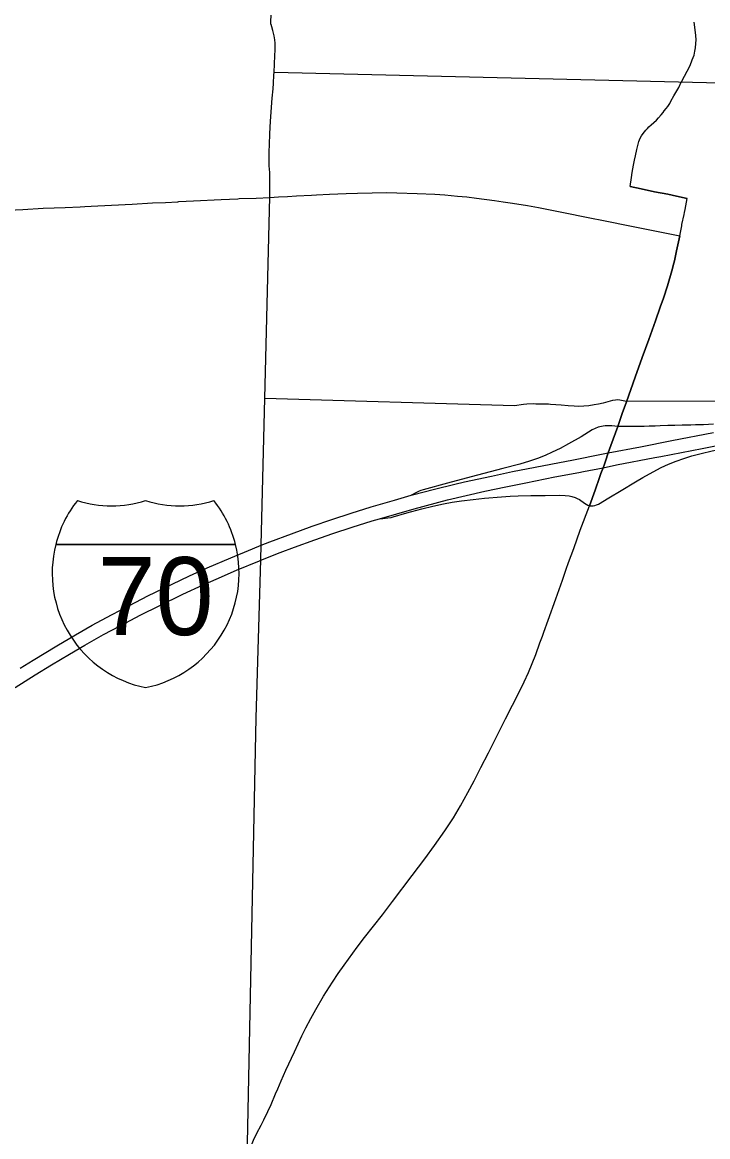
# Model space of a CAD drawing. Extents: x -29.6 to 34, y 0 to 22.
# Drawn here: x 11.502 to 12.723, y 15.537 to 17.521 of the extents above; entities that cross this region are included whole.
import ezdxf

# ---------------------------------------------------------------- set-up
doc = ezdxf.new("R2010")
doc.units = 0
for name, color, linetype in [('GM_X_Corporation', 7, 'Continuous'), ('GM_X_County_Road', 7, 'Continuous'), ('GM_X_Interchange_Ramps', 7, 'Continuous'), ('GM_X_Interstate_Route', 7, 'Continuous'), ('GM_X_Interstate_Shield', 7, 'Continuous'), ('GM_X_State_Route', 7, 'Continuous'), ('GM_X_Township', 7, 'Continuous'), ('GM_X_US_Route', 7, 'Continuous')]:
    doc.layers.add(name, color=color, linetype=linetype)

msp = doc.modelspace()

# ---------------------------------------------------------------- linework, layer by layer
at = {"layer": 'GM_X_Corporation'}
msp.add_lwpolyline([(13.0031, 16.8467), (12.5779, 16.8459), (12.5663, 16.8482), (12.5627, 16.8484), (12.5584, 16.8481), (12.5534, 16.8472), (12.545, 16.8452), (12.5365, 16.843), (12.5282, 16.8411), (12.5203, 16.8396), (12.5108, 16.8382), (12.5021, 16.8373), (12.4934, 16.837), (12.4847, 16.8372), (12.4745, 16.8379), (12.4615, 16.8392), (12.452, 16.8399), (12.4426, 16.8405), (12.439, 16.8407), (12.4317, 16.841), (12.4282, 16.8411), (12.4246, 16.8411), (12.4195, 16.8412), (12.4167, 16.8412), (12.412, 16.8413), (12.4005, 16.8408), (12.3944, 16.8403), (12.3786, 16.8382), (11.934, 16.851), (11.9428, 17.2098), (11.9426, 17.2539), (11.9422, 17.2585), (11.9418, 17.2657), (11.9416, 17.2766), (11.9418, 17.2904), (11.9421, 17.3035), (11.9429, 17.3224), (11.9441, 17.3449), (11.9472, 17.3855), (11.9485, 17.4022), (11.9493, 17.4123), (11.95, 17.4269), (11.9503, 17.4323), (13.54, 17.394)], dxfattribs=at)
at = {"layer": 'GM_X_County_Road'}
msp.add_lwpolyline([(12.5846, 17.2282), (12.604, 17.2242), (12.6282, 17.2192), (12.6517, 17.2146), (12.6674, 17.2113), (12.6862, 17.2073)], dxfattribs=at)
at = {"layer": 'GM_X_Interchange_Ramps'}
for points in [[(12.7333, 16.8051), (12.7151, 16.8044), (12.7013, 16.8039), (12.6926, 16.8036), (12.689, 16.8035), (12.6773, 16.8033), (12.6643, 16.8029), (12.6519, 16.8027), (12.6381, 16.8022), (12.6294, 16.8019), (12.6185, 16.8017), (12.6097, 16.8014), (12.5952, 16.8011), (12.5726, 16.8014), (12.5625, 16.8015)], [(12.5625, 16.8015), (12.5521, 16.8021), (12.5438, 16.8025), (12.5404, 16.8024), (12.5368, 16.802), (12.5334, 16.8015), (12.5278, 16.7998), (12.5224, 16.7976), (12.5172, 16.795), (12.5103, 16.791), (12.4972, 16.7831), (12.4751, 16.7704), (12.4597, 16.7621), (12.446, 16.7554), (12.4334, 16.7498), (12.4199, 16.7444), (12.4054, 16.7395), (12.3879, 16.7344), (12.3577, 16.7264), (12.3013, 16.7118), (12.2591, 16.7005), (12.2159, 16.6885), (12.2118, 16.6872), (12.2087, 16.6861), (12.2051, 16.6844), (12.2004, 16.682), (12.1964, 16.6798), (12.1948, 16.6788)], [(12.138, 16.6371), (12.1442, 16.6376), (12.1481, 16.638), (12.1531, 16.6384), (12.1587, 16.6394), (12.1624, 16.6405), (12.1869, 16.6474), (12.2136, 16.6547), (12.2334, 16.6595), (12.2519, 16.6635), (12.2677, 16.6663), (12.2842, 16.6688), (12.3052, 16.6714), (12.3255, 16.6734), (12.3552, 16.676), (12.3712, 16.6771), (12.385, 16.6777), (12.4076, 16.6781), (12.4331, 16.6785), (12.4585, 16.6788), (12.4687, 16.6785), (12.476, 16.6777), (12.481, 16.6767), (12.4865, 16.675), (12.4905, 16.6732), (12.4943, 16.6711), (12.5035, 16.6647), (12.5064, 16.6628), (12.5095, 16.6611), (12.512, 16.6602)]]:
    msp.add_lwpolyline(points, dxfattribs=at)
at = {"layer": 'GM_X_Interstate_Route'}
for points in [[(12.1948, 16.6788), (12.1968, 16.6794), (12.2362, 16.6898), (12.2722, 16.6987), (12.2893, 16.7026), (12.3376, 16.7128), (12.3753, 16.7211), (12.4839, 16.7417), (12.5339, 16.7519), (12.5457, 16.7542), (12.6028, 16.7653), (12.6588, 16.7765), (12.7332, 16.7906)], [(12.6289, 16.7458), (12.6394, 16.7478), (12.7132, 16.762), (12.7873, 16.7769), (12.8491, 16.7884), (12.9014, 16.7988), (12.9093, 16.8006)], [(12.4934, 16.7194), (12.5015, 16.7209), (12.5365, 16.7279), (12.5605, 16.7327), (12.6289, 16.7458)], [(12.138, 16.6371), (12.2001, 16.6545), (12.2592, 16.6707), (12.326, 16.6863), (12.3633, 16.694), (12.3986, 16.7012), (12.4503, 16.7114), (12.4934, 16.7194)], [(11.4984, 16.3712), (11.5212, 16.3854), (11.5636, 16.411), (11.5969, 16.4305), (11.6266, 16.4474), (11.6605, 16.4658), (11.6927, 16.4828), (11.7258, 16.4995), (11.769, 16.5206), (11.7999, 16.5352), (11.831, 16.5493), (11.8731, 16.5675), (11.9121, 16.5836), (11.9275, 16.5897), (11.9426, 16.5956), (11.9814, 16.6103), (12.0183, 16.6236), (12.0534, 16.6357), (12.088, 16.6471), (12.1234, 16.6582), (12.1646, 16.6703), (12.1948, 16.6788)], [(11.4893, 16.3363), (11.5249, 16.3591), (11.554, 16.3771), (11.5859, 16.3961), (11.613, 16.4118), (11.6467, 16.4307), (11.6762, 16.4466), (11.7129, 16.4659), (11.7455, 16.4822), (11.7881, 16.5028), (11.8238, 16.5193), (11.8471, 16.5297), (11.8832, 16.5452), (11.9243, 16.5621), (11.9269, 16.5632), (11.9615, 16.5769), (11.9867, 16.5865), (12.023, 16.5996), (12.0553, 16.6108), (12.0892, 16.622), (12.1254, 16.6333), (12.138, 16.6371)]]:
    msp.add_lwpolyline(points, dxfattribs=at)
at = {"layer": 'GM_X_Interstate_Shield'}
for p, q in [((11.5615, 16.5912), (11.8817, 16.5912)), ((11.8817, 16.5912), (11.5615, 16.5912)), ((11.8817, 16.5912), (11.5615, 16.5912))]:
    msp.add_line(p, q, dxfattribs=at)
for centre, start, end in [((11.7632, 16.5402), 141.669, 165.8066), ((11.6608, 16.8682), 253.0091, 286.9909), ((11.7824, 16.8682), 253.0091, 286.9909), ((11.68, 16.5402), 14.1934, 38.331), ((11.7632, 16.5402), 165.8066, 258.463), ((11.68, 16.5402), 281.537, 14.1934)]:
    msp.add_arc(centre, 0.2081, start, end, dxfattribs=at)
at = {"layer": 'GM_X_State_Route'}
msp.add_line((12.6675, 17.1137), (12.6729, 17.1404), dxfattribs=at)
for points in [[(12.6763, 17.415), (12.6913, 17.4441), (12.6954, 17.4537), (12.6984, 17.4621), (12.7001, 17.4694), (12.7009, 17.4753), (12.7018, 17.4828), (12.7021, 17.4895), (12.7019, 17.4971), (12.7007, 17.5074), (12.6985, 17.5213)], [(12.5846, 17.2282), (12.5871, 17.2446), (12.5885, 17.2534), (12.5909, 17.2662), (12.5925, 17.2751), (12.594, 17.2832), (12.5965, 17.2946), (12.5987, 17.3039), (12.6002, 17.3088), (12.6024, 17.3143), (12.6049, 17.3188), (12.6078, 17.3231), (12.6125, 17.3288), (12.6155, 17.3319), (12.6181, 17.3345), (12.6218, 17.338), (12.6315, 17.3466), (12.6354, 17.3508), (12.6401, 17.3562), (12.6433, 17.3601), (12.6455, 17.363), (12.6489, 17.3676), (12.6515, 17.3711), (12.6551, 17.3765), (12.6573, 17.3802), (12.6627, 17.3896), (12.6712, 17.4049), (12.6758, 17.414), (12.6763, 17.415)], [(12.6862, 17.2073), (12.6674, 17.2113), (12.6517, 17.2146), (12.6282, 17.2192), (12.604, 17.2242), (12.5846, 17.2282)], [(12.6729, 17.1404), (12.6765, 17.1587), (12.6769, 17.1607), (12.6806, 17.1788), (12.6814, 17.1824), (12.6824, 17.1873), (12.6862, 17.2073)], [(12.5781, 16.8453), (12.5937, 16.8892), (12.606, 16.9242), (12.6178, 16.9563), (12.6296, 16.9892), (12.6384, 17.0138), (12.644, 17.0295), (12.6512, 17.0516), (12.6591, 17.0781), (12.6626, 17.0921), (12.6636, 17.0961), (12.6675, 17.1137)], [(12.5625, 16.8015), (12.5705, 16.8242), (12.5781, 16.8453)], [(12.548, 16.7608), (12.5502, 16.7675), (12.5625, 16.8015)], [(12.512, 16.6602), (12.5222, 16.6879), (12.5302, 16.7105), (12.5327, 16.7173), (12.5365, 16.7279), (12.5381, 16.7324), (12.5405, 16.7393), (12.5457, 16.7542), (12.548, 16.7608)], [(11.9631, 15.6363), (11.9716, 15.6556), (11.9865, 15.688), (11.9998, 15.7163), (12.0068, 15.7307), (12.0156, 15.7474), (12.0245, 15.7633), (12.0386, 15.787), (12.0546, 15.8122), (12.0647, 15.8274), (12.0752, 15.8422), (12.0983, 15.874), (12.1114, 15.8914), (12.1433, 15.9321), (12.1614, 15.9558), (12.1962, 16.0016), (12.2191, 16.0318), (12.2363, 16.0553), (12.2548, 16.0815), (12.2629, 16.0936), (12.2699, 16.1048), (12.2825, 16.1261), (12.2956, 16.1497), (12.3066, 16.1702), (12.3189, 16.1943), (12.3322, 16.2201), (12.3468, 16.2487), (12.3628, 16.2805), (12.3875, 16.3293), (12.3961, 16.3469), (12.4037, 16.3635), (12.4102, 16.379), (12.4165, 16.3953), (12.424, 16.4158), (12.4285, 16.4281), (12.4311, 16.4349), (12.4385, 16.4563), (12.452, 16.4947), (12.4641, 16.5275), (12.4708, 16.5475), (12.4751, 16.5591), (12.4846, 16.5843), (12.4955, 16.6168), (12.512, 16.6602)], [(11.9028, 15.4967), (11.9042, 15.5029), (11.9067, 15.5119), (11.91, 15.5215), (11.9139, 15.5308), (11.9198, 15.5432), (11.9272, 15.5574), (11.9323, 15.5671), (11.9394, 15.5815), (11.9451, 15.5941), (11.9531, 15.6129), (11.9571, 15.6222), (11.9631, 15.6363)]]:
    msp.add_lwpolyline(points, dxfattribs=at)
at = {"layer": 'GM_X_Township'}
msp.add_lwpolyline([(11.9023, 15.4963), (11.9182, 16.2825), (11.9267, 16.5638), (11.9276, 16.5905), (11.934, 16.851), (11.9428, 17.2098), (11.9426, 17.2539), (11.9422, 17.2585), (11.9418, 17.2657), (11.9416, 17.2766), (11.9418, 17.2904), (11.9421, 17.3035), (11.9429, 17.3224), (11.9441, 17.3449), (11.9472, 17.3855), (11.9485, 17.4022), (11.9493, 17.4123), (11.95, 17.4269), (11.9503, 17.4323), (11.951, 17.4465), (11.9513, 17.4501), (11.9519, 17.458), (11.9525, 17.4748), (11.9524, 17.4835), (11.9517, 17.4893), (11.9504, 17.4964), (11.948, 17.5063), (11.9465, 17.5127), (11.9452, 17.5168), (11.9448, 17.5176), (11.975, 18.5989)], dxfattribs=at)
at = {"layer": 'GM_X_US_Route'}
msp.add_line((12.6729, 17.1404), (12.6675, 17.1137), dxfattribs=at)
for points in [[(11.4628, 17.1858), (11.5026, 17.1878), (11.5393, 17.1897), (11.5782, 17.1912), (11.6047, 17.1925), (11.6132, 17.193), (11.6247, 17.1936), (11.6605, 17.1955), (11.6977, 17.1973), (11.7338, 17.1991), (11.7572, 17.2001), (11.7792, 17.2014), (11.7808, 17.2015), (11.807, 17.2027), (11.8563, 17.2052), (11.8859, 17.2067)], [(11.8859, 17.2067), (11.8882, 17.2069), (11.9184, 17.2079), (11.943, 17.2091), (11.9581, 17.2099)], [(11.9581, 17.2099), (11.9744, 17.2109), (11.9901, 17.2119), (12.017, 17.2132), (12.0261, 17.2136)], [(12.0261, 17.2136), (12.0489, 17.2146), (12.0788, 17.216), (12.0991, 17.2168), (12.1253, 17.2173), (12.1515, 17.2175), (12.1689, 17.2173), (12.2053, 17.2161), (12.2365, 17.2146), (12.2547, 17.2134), (12.2772, 17.2115), (12.2938, 17.2099), (12.3111, 17.2077), (12.3429, 17.2035), (12.3587, 17.2013), (12.3748, 17.1988)], [(12.3748, 17.1988), (12.4018, 17.1945), (12.4211, 17.191), (12.4689, 17.1815), (12.5067, 17.1738), (12.5432, 17.1666), (12.581, 17.1591), (12.6317, 17.1488), (12.6642, 17.1422), (12.6729, 17.1404)], [(12.6675, 17.1137), (12.6636, 17.0961), (12.6626, 17.0921), (12.6591, 17.0781), (12.6512, 17.0516), (12.644, 17.0295), (12.6384, 17.0138), (12.6296, 16.9892), (12.6178, 16.9563), (12.606, 16.9242), (12.5937, 16.8892), (12.5781, 16.8453)], [(12.5781, 16.8453), (12.5705, 16.8242), (12.5625, 16.8015)], [(12.5625, 16.8015), (12.5502, 16.7675), (12.548, 16.7608)], [(12.5942, 16.7026), (12.6071, 16.7103), (12.6255, 16.7207), (12.6398, 16.7281), (12.653, 16.7342), (12.6665, 16.7397), (12.6802, 16.7445), (12.6948, 16.749), (12.711, 16.7533), (12.7309, 16.758), (12.8178, 16.7765), (12.8541, 16.7843), (12.8981, 16.7949), (12.9026, 16.7962), (12.9063, 16.7979), (12.9078, 16.7989), (12.9093, 16.8006)], [(12.548, 16.7608), (12.5457, 16.7542), (12.5405, 16.7393), (12.5381, 16.7324), (12.5365, 16.7279), (12.5327, 16.7173), (12.5302, 16.7105), (12.5222, 16.6879), (12.512, 16.6602)], [(12.512, 16.6602), (12.5154, 16.6599), (12.5185, 16.6601), (12.5215, 16.6608), (12.5248, 16.6617), (12.5282, 16.6632), (12.5464, 16.6742), (12.5684, 16.6872), (12.5942, 16.7026)]]:
    msp.add_lwpolyline(points, dxfattribs=at)

# ---------------------------------------------------------------- texts
at = {"layer": 'GM_X_Interstate_Shield'}
msp.add_text('70', height=0.13872, dxfattribs=at).set_placement((11.6363, 16.4299))

doc.saveas('drawing.dxf')
